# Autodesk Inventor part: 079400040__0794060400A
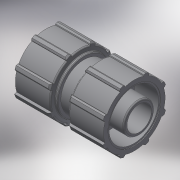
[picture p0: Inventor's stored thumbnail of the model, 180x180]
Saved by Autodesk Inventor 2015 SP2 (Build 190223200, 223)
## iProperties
Created: 2017-04
Part Number: 079400040__0794060400A
Material: Generic
Description: PLASSON MODULAR ADAPTOR 40
Document SubType Name: Modeling
Designer: KIM
Mass: 245.995 g
Surface Area: 626.128 cm^2
Volume: 245.995 cm^3
Density: 1 g/cm^3
Appearance: Default
Author: KIM
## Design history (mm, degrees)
derived "07940.ipt"
feature "Solid1::07940.ipt"
tag "TaggingFeature1"
body "Solid1"
other parameters: "d7" = 82, "d8" = 65.6, "d15" = 61.5, "d17" = 40.8, "d43" = 100 deg, "d46" = 76.26, "d47" = 35 deg, "d48" = 17.5 deg, "d50" = 0, "d52" = 360 deg, "d54" = 1.64, "d57" = 1.64, "d68" = 36.72, "d69" = 0.5, "d70" = 3.672, "d71" = 5, "d72" = 32, "d73" = 51, "d74" = 45.9, "d75" = 57.4, "d76" = 0.82, "d77" = 1.64, "d79" = 360 deg, "d81" = 1.64, "d82" = 20.4, "E_" = 82, "H_" = 102
